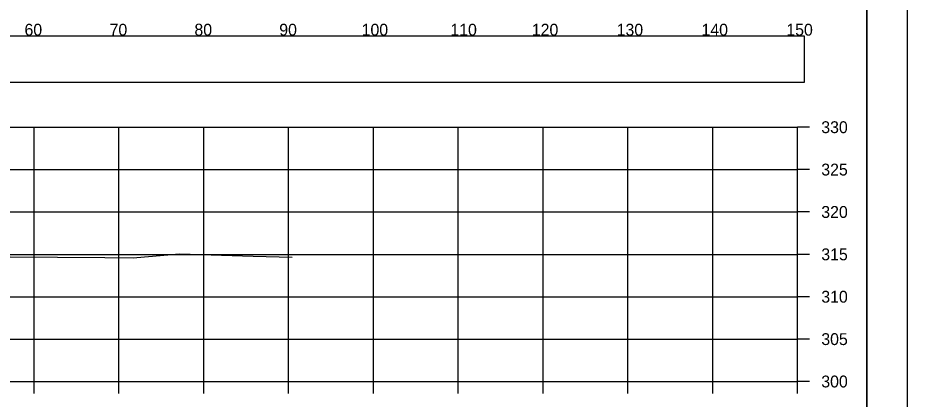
# Model space of a CAD drawing. Extents: x 1376273 to 1384221, y 378927 to 384592.
# Drawn here: x 1380615.9 to 1380720.8, y 380218.7 to 380263.7 of the extents above; entities that cross this region are included whole.
import ezdxf

# ---------------------------------------------------------------- set-up
doc = ezdxf.new("R2010")
doc.units = 0
for name, color, linetype in [('R_Axis', 7, 'Continuous'), ('R_Axis Annot', 7, 'Continuous'), ('R_Border', 7, 'Continuous'), ('R_Exist Surface', 7, 'Continuous'), ('R_Grid', 7, 'Continuous'), ('R_No Plot', 7, 'Continuous')]:
    doc.layers.add(name, color=color, linetype=linetype)

msp = doc.modelspace()

# ---------------------------------------------------------------- linework, layer by layer
at = {"layer": 'R_Axis'}
for p, q in [((1380707.84, 380220.82), (1380707.84, 380250.82)), ((1380709.24, 380250.82), (1380707.84, 380250.82)), ((1380709.24, 380245.82), (1380707.84, 380245.82)), ((1380709.24, 380240.82), (1380707.84, 380240.82)), ((1380709.24, 380235.82), (1380707.84, 380235.82)), ((1380709.24, 380230.82), (1380707.84, 380230.82)), ((1380709.24, 380225.82), (1380707.84, 380225.82)), ((1380407.84, 380220.82), (1380707.84, 380220.82)), ((1380617.84, 380219.42), (1380617.84, 380220.82)), ((1380627.84, 380219.42), (1380627.84, 380220.82)), ((1380637.84, 380219.42), (1380637.84, 380220.82)), ((1380647.84, 380219.42), (1380647.84, 380220.82)), ((1380657.84, 380219.42), (1380657.84, 380220.82)), ((1380667.84, 380219.42), (1380667.84, 380220.82)), ((1380677.84, 380219.42), (1380677.84, 380220.82)), ((1380687.84, 380219.42), (1380687.84, 380220.82)), ((1380697.84, 380219.42), (1380697.84, 380220.82)), ((1380707.84, 380219.42), (1380707.84, 380220.82)), ((1380709.24, 380220.82), (1380707.84, 380220.82))]:
    msp.add_line(p, q, dxfattribs=at)
at = {"layer": 'R_Axis Annot'}
msp.add_lwpolyline([(1380406.97, 380256.14), (1380708.66, 380256.14), (1380708.66, 380261.55), (1380406.97, 380261.55)], close=True, dxfattribs=at)
at = {"layer": 'R_Border'}
msp.add_line((1380716.02, 380115.82), (1380716.02, 380321.28), dxfattribs=at)
at = {"layer": 'R_Exist Surface'}
msp.add_lwpolyline([(1380615.03, 380235.51), (1380626.19, 380235.43), (1380629.58, 380235.41), (1380629.96, 380235.43), (1380635, 380235.88), (1380643.66, 380235.59), (1380648.29, 380235.47)], dxfattribs=at)
at = {"layer": 'R_Grid'}
for p, q in [((1380407.84, 380250.82), (1380707.84, 380250.82)), ((1380617.84, 380220.82), (1380617.84, 380250.82)), ((1380627.84, 380220.82), (1380627.84, 380250.82)), ((1380637.84, 380220.82), (1380637.84, 380250.82)), ((1380647.84, 380220.82), (1380647.84, 380250.82)), ((1380657.84, 380220.82), (1380657.84, 380250.82)), ((1380667.84, 380220.82), (1380667.84, 380250.82)), ((1380677.84, 380220.82), (1380677.84, 380250.82)), ((1380687.84, 380220.82), (1380687.84, 380250.82)), ((1380697.84, 380220.82), (1380697.84, 380250.82)), ((1380707.84, 380220.82), (1380707.84, 380250.82)), ((1380407.84, 380245.82), (1380707.84, 380245.82)), ((1380407.84, 380240.82), (1380707.84, 380240.82)), ((1380407.84, 380235.82), (1380707.84, 380235.82)), ((1380407.84, 380230.82), (1380707.84, 380230.82)), ((1380407.84, 380225.82), (1380707.84, 380225.82)), ((1380407.84, 380220.82), (1380707.84, 380220.82))]:
    msp.add_line(p, q, dxfattribs=at)
at = {"layer": 'R_No Plot'}
for points in [[(1380387.43, 380325.17), (1380720.77, 380325.17), (1380720.77, 380111.84), (1380387.43, 380111.84)], [(1380633.76, 380321.28), (1380633.76, 380311.4), (1380669.49, 380311.4), (1380669.49, 380308.48), (1380692.69, 380308.48), (1380692.69, 380284.15), (1380716.02, 380284.15), (1380716.02, 380115.82), (1380399.84, 380115.82), (1380399.84, 380321.28)]]:
    msp.add_lwpolyline(points, close=True, dxfattribs=at)

# ---------------------------------------------------------------- texts
at = {"layer": 'R_Axis Annot'}
for s, p in [('60', (1380616.72, 380261.62)), ('70', (1380626.75, 380261.62)), ('80', (1380636.75, 380261.62)), ('90', (1380646.75, 380261.62)), ('100', (1380656.46, 380261.62)), ('110', (1380666.92, 380261.62)), ('120', (1380676.52, 380261.62)), ('130', (1380686.52, 380261.62)), ('140', (1380696.52, 380261.62)), ('150', (1380706.52, 380261.62)), ('330', (1380710.64, 380250.12)), ('325', (1380710.64, 380245.12)), ('320', (1380710.64, 380240.12)), ('315', (1380710.64, 380235.12)), ('310', (1380710.64, 380230.12)), ('305', (1380710.64, 380225.12)), ('300', (1380710.64, 380220.12))]:
    msp.add_text(s, height=1.4, dxfattribs=at).set_placement(p)

doc.saveas('drawing.dxf')
